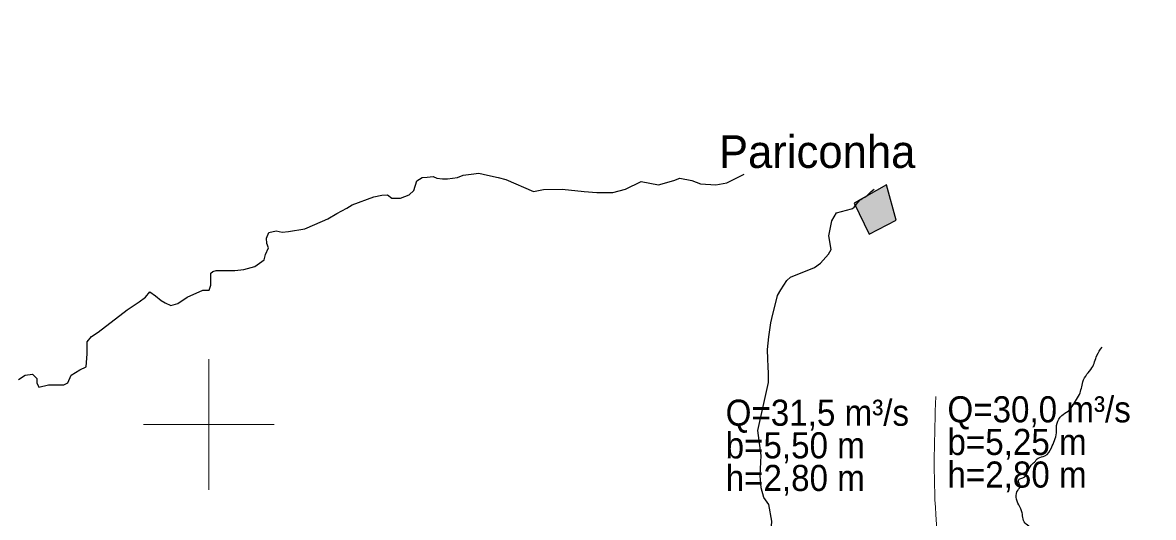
# Model space of a CAD drawing. Extents: x -1643653 to 4543381, y 1624270 to 13878484.
# Drawn here: x 597147 to 614474, y 8973576 to 8981162 of the extents above; entities that cross this region are included whole.
import ezdxf

# ---------------------------------------------------------------- set-up
doc = ezdxf.new("R2010")
doc.units = 0
doc.header["$LTSCALE"] = 160
for name, color, linetype, lineweight in [('2', 7, 'Continuous', 13), ('21', 7, 'Continuous', 25), ('24', 7, 'Continuous', 25), ('50', 7, 'Continuous', 13), ('60', 7, 'Continuous', 13)]:
    doc.layers.add(name, color=color, linetype=linetype, lineweight=lineweight)
doc.layers.add('41', color=7, linetype='Continuous')

msp = doc.modelspace()

# ---------------------------------------------------------------- hatches: boundary and pattern name
at = {"layer": '21'}
msp.add_hatch(color=256, dxfattribs=at).paths.add_polyline_path([(609890.7, 8978396.1), (610117.7, 8977916.4), (610532.2, 8978134.8), (610383.5, 8978676.2)])

# ---------------------------------------------------------------- linework, layer by layer
at = {"layer": '2'}
for p, q in [((600000, 8974000), (600000, 8976000)), ((599000, 8975000), (601000, 8975000))]:
    msp.add_line(p, q, dxfattribs=at)
at = {"layer": '21'}
msp.add_lwpolyline([(609890.7, 8978396.1), (610117.7, 8977916.4), (610532.2, 8978134.8), (610383.5, 8978676.2)], close=True, dxfattribs=at)
at = {"layer": '24'}
msp.add_line((609963.1, 8978425.2), (609985.3, 8978448.2), dxfattribs=at)
for points in [[(603809.3, 8978786.7), (603897.3, 8978823.4), (604022, 8978838.1), (604139.3, 8978852.8), (604271.3, 8978823.4), (604432.7, 8978786.7), (604550, 8978757.3), (604975, 8978572.4)], [(604975, 8978572.4), (605129.4, 8978603.2), (605415.4, 8978610.6), (605752.7, 8978573.9), (605943.4, 8978559.2), (606192.7, 8978559.2), (606383.4, 8978610.6), (606625.4, 8978728), (606889.4, 8978676.6), (607124.1, 8978742.7), (607219.4, 8978779.4), (607402.8, 8978742.7), (607534.8, 8978691.3), (607769.4, 8978676.6), (607938.1, 8978706), (608202.1, 8978838.1)], [(602527.9, 8978491.8), (602650.6, 8978515.2), (602738.6, 8978522.5), (602804.6, 8978471.2), (602936.6, 8978471.2), (603068.6, 8978522.5), (603142, 8978588.6), (603186, 8978735.3), (603266.7, 8978786.7), (603347.3, 8978794), (603435.3, 8978801.4), (603494, 8978779.4), (603582, 8978764.7), (603655.3, 8978764.7), (603809.3, 8978786.7)], [(597084.7, 8975689.4), (597183.4, 8975755.3), (597298.6, 8975771.7), (597364.4, 8975705.9), (597364.4, 8975640), (597397.3, 8975574.2), (597545.3, 8975607.1), (597627.6, 8975607.1), (597775.7, 8975607.1), (597841.5, 8975640), (597890.8, 8975755.3), (598022.4, 8975837.6), (598121.1, 8975887), (598137.6, 8976084.5), (598137.6, 8976265.6), (598203.4, 8976347.9), (598302.1, 8976413.7), (598746.2, 8976759.4), (598932.5, 8976878.8), (599027.9, 8976952.2), (599093.9, 8977032.9), (599181.9, 8976974.2), (599269.9, 8976900.8), (599328.6, 8976864.1), (599416.6, 8976827.4), (599526.6, 8976856.8), (599665.9, 8976952.2), (599907.9, 8977062.2), (600003.2, 8977062.2), (600032.6, 8977135.6), (600032.6, 8977238.3), (600032.6, 8977319.1), (600061.9, 8977348.4), (600113.2, 8977363.1), (600274.6, 8977363.1), (600399.2, 8977363.1), (600538.6, 8977377.8), (600707.2, 8977421.8), (600846.6, 8977524.5), (600868.6, 8977605.3), (600912.6, 8977708), (600890.6, 8977774), (600883.2, 8977854.8), (600919.9, 8977942.8), (601029.9, 8977972.2), (601125.3, 8977950.2), (601220.6, 8977957.5), (601469.9, 8978001.5), (601623.9, 8978067.6), (601821.9, 8978155.6), (601961.3, 8978236.3), (602115.3, 8978317.1), (602196, 8978368.4), (602527.9, 8978491.8)], [(609988.6, 8978451.5), (610010.3, 8978466.5), (610061.1, 8978489.5), (610086.1, 8978510.5), (610150.8, 8978570.6), (610195.3, 8978607.5)], [(608764.9, 8977065.1), (608854.4, 8977208), (608912.6, 8977261.5), (609281.4, 8977407.7), (609370.8, 8977473.7), (609493.8, 8977609.5), (609536.2, 8977684.1), (609500.2, 8977893.9), (609548.1, 8978125.2), (609619.8, 8978247.6), (609848.8, 8978304.7), (609863.5, 8978311.5), (609888.4, 8978332.5), (609966.3, 8978428.5)], [(608626.7, 8976624.4), (608712.1, 8976980.7), (608764.9, 8977065.1)], [(608573.2, 8975888.4), (608564.5, 8976001.3), (608562, 8976152), (608579.7, 8976343.3), (608594.9, 8976450.9), (608611.3, 8976558.6), (608626.7, 8976624.4)], [(608412.1, 8974909.8), (608578.3, 8975642.7), (608577.2, 8975782.8), (608573.2, 8975888.4)], [(607981.4, 8972045.9), (608340.3, 8972373.2), (608504, 8972626.3), (608557, 8972753.5), (608584.6, 8972880.9), (608629.2, 8973517.9), (608582.5, 8973773.1), (608506, 8973879.6), (608465.7, 8974028), (608448.7, 8974219.2), (608463.5, 8974525.1), (608412.1, 8974909.8)]]:
    msp.add_lwpolyline(points, dxfattribs=at)
for points in [[(612653, 8974423.1), (612709.6, 8974484.8), (612812.4, 8974520.8), (612910, 8974644.2), (612987.1, 8974870.5), (612997.4, 8975019.7), (613069.4, 8975138), (613167, 8975204.8), (613280.1, 8975359.1), (613341.8, 8975462), (613393.2, 8975652.3), (613454.9, 8975770.6), (613532, 8975868.3), (613609.1, 8976058.6), (613686.2, 8976187.2)], [(612667.9, 8967747.4), (612667.9, 8967790.6), (612680.2, 8967833.7), (612689.4, 8967892.3), (612701.8, 8967938.6), (612692.5, 8967987.9), (612692.5, 8968024.9), (612726.4, 8968049.6), (612775.7, 8968098.9), (612785, 8968114.3), (612741.8, 8968172.9), (612704.8, 8968231.5), (612692.5, 8968339.4), (612692.5, 8968425.8), (612738.8, 8968487.5), (612781.9, 8968533.7), (612694.2, 8968580), (612482.9, 8968630.8), (612373, 8968664.6), (612212.4, 8969002.9), (612043.3, 8969189), (611899.7, 8969349.7), (611882.8, 8969392), (612026.5, 8969392), (612187.1, 8969451.2), (612254.7, 8969544.2), (612204, 8969662.7), (612077.2, 8969984.1), (612026.5, 8970153.2), (611967.3, 8970271.6), (612018, 8970415.4), (612059.6, 8970464.8), (612178.6, 8970464.8), (612198.5, 8970524.3), (612143.9, 8970638.6), (612134, 8970737.9), (612183.6, 8970832.2), (612198.5, 8970901.7), (612173.7, 8970996.1), (612153.8, 8971095.4), (612034.7, 8971169.8), (611950.4, 8971234.4), (611811.4, 8971313.8), (611756.8, 8971358.5), (611742, 8971462.8), (611712.2, 8971557.2), (611702.3, 8971636.6), (611756.8, 8971686.2), (611801.5, 8971686.2), (611829.2, 8971666.8), (611881.3, 8971661.6), (611964.6, 8971705.9), (612040.2, 8971737.1), (612128.7, 8971752.8), (612212, 8971778.8), (612238.1, 8971812.7), (612258.9, 8971872.6), (612264.1, 8971989.9), (612258.9, 8972052.5), (612245.9, 8972091.6), (612199, 8972120.2), (612087, 8972203.6), (612029.7, 8972268.8), (611993.3, 8972341.7), (612000.3, 8972381.2), (612077.3, 8972484.1), (612113.3, 8972556.1), (612180.2, 8972607.5), (612231.6, 8972664.1), (612288.1, 8972725.8), (612318.9, 8972792.7), (612396, 8972854.4), (612426.9, 8972905.8), (612468, 8973024.1), (612498.8, 8973137.3), (612550.2, 8973199), (612601.6, 8973286.4), (612606.8, 8973368.7), (612596.5, 8973409.9), (612524.5, 8973471.6), (612478.3, 8973553.9), (612462.8, 8973646.5), (612370.3, 8973888.2), (612396, 8973991.1), (612432, 8974057.9), (612406.3, 8974140.2), (612416.6, 8974160.8), (612473.1, 8974181.4), (612555.4, 8974299.7), (612622.2, 8974397.4), (612653, 8974423.1)]]:
    msp.add_spline(points, degree=3, dxfattribs=at)
at = {"layer": '50'}
msp.add_spline([(610965.5, 8970053.3), (611331.2, 8971315.6), (611274, 8972409), (611139.3, 8973619.8), (611139.3, 8975430.3)], degree=3, dxfattribs=at)
at = {"layer": '60', "lineweight": 25}
msp.add_spline([(814781, 9009175.5), (814787.2, 9009173.4), (814796.9, 9009173.4), (814799.4, 9009172.4), (814805.1, 9009174.5), (814805.6, 9009176.5), (814811.7, 9009179.5), (814811.7, 9009179.5), (814801.5, 9009181), (814790.7, 9009181.5), (814784.1, 9009183.1), (814777.4, 9009185.1), (814778.4, 9009175.5)], degree=3, dxfattribs=at)

# ---------------------------------------------------------------- texts
at = {"layer": '41'}
msp.add_text('Pariconha', height=500, dxfattribs=at).set_placement((607816.3, 8978933.9))
at = {"layer": '50', "width": 0.95}
for s, p in [('Q=31,5 m³/s', (607919.4, 8974981.3)), ('Q=30,0 m³/s', (611317.6, 8975033.4)), ('b=5,50 m', (607919.4, 8974481.3)), ('b=5,25 m', (611317.6, 8974533.4)), ('h=2,80 m', (607919.4, 8973981.3)), ('h=2,80 m', (611317.6, 8974033.4))]:
    msp.add_text(s, height=400, dxfattribs=at).set_placement(p)

doc.saveas('drawing.dxf')
